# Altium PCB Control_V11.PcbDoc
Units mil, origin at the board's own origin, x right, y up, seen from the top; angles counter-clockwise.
Board outline 4960.63 x 3543.31 mil, 2 copper layers (TopLayer, BottomLayer); 68 components, 61 nets, 280 pads, 236 vias.
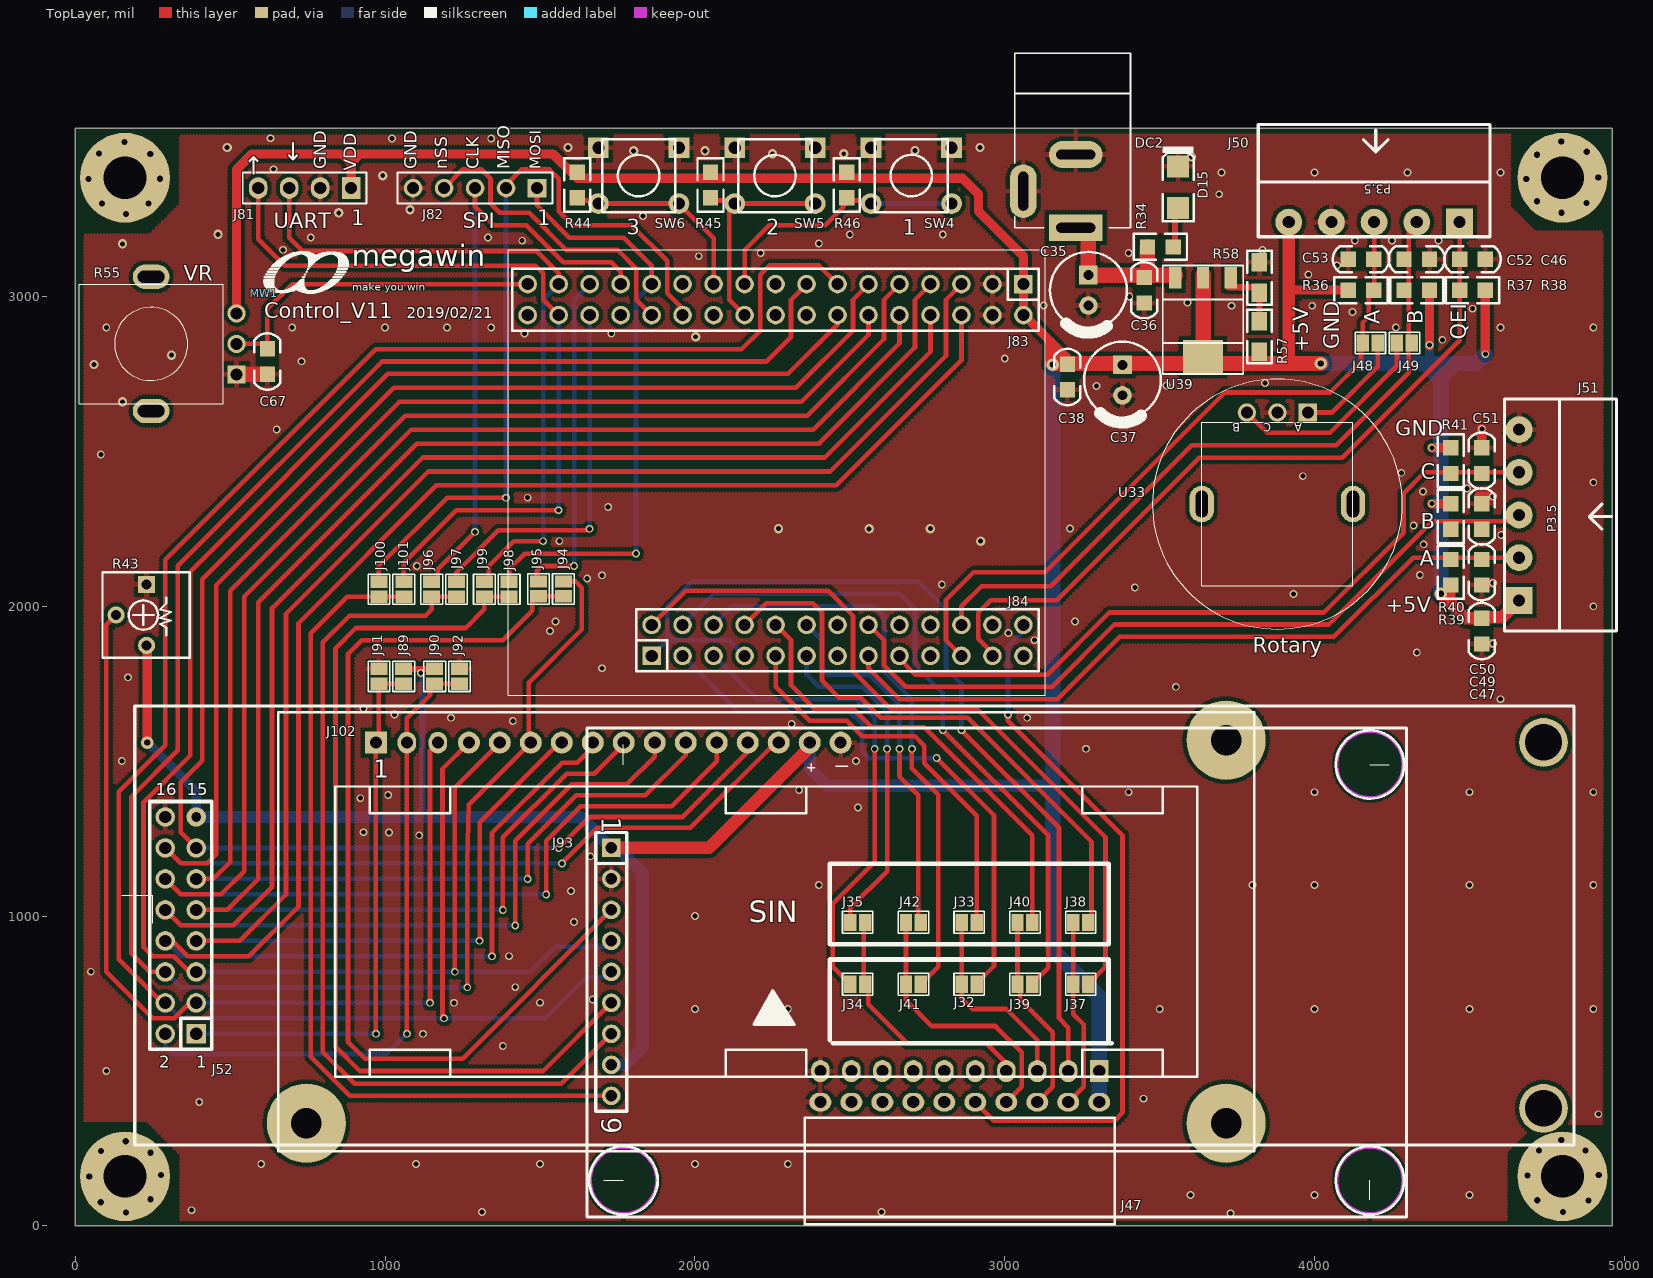
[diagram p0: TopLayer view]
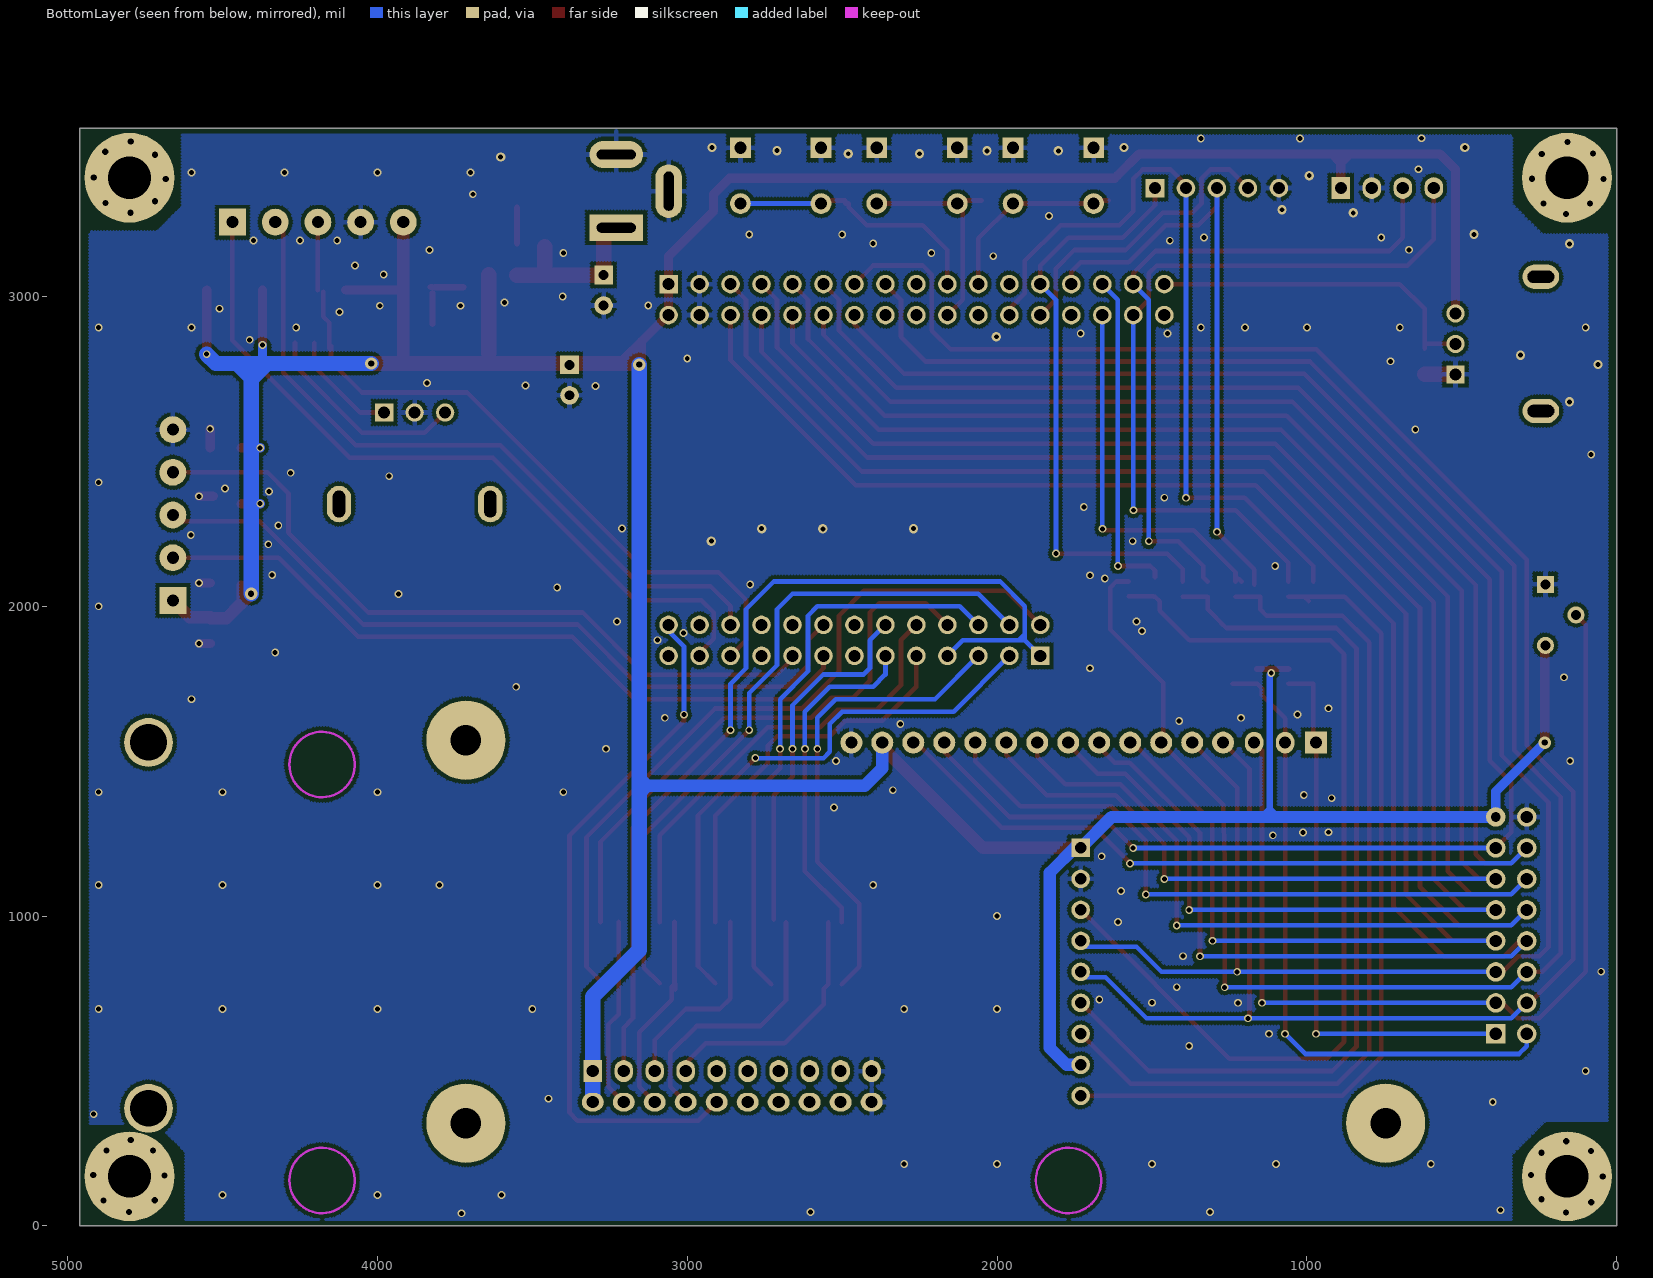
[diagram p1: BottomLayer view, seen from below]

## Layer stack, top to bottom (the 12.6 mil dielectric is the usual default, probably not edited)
TopLayer: signal copper 1.4
Dielectric: dielectric 12.6, FR-4, Dk 4.8
BottomLayer: signal copper 1.4

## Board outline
0,0 0,3543.31 4960.63,3543.31 4960.63,0

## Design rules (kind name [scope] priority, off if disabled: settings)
Clearance 20 [All] p1 off: gap=20
Clearance 12 [All] p2 off: gap=12
Clearance 6 [All] p3: gap=6
FabricationTestPointUsage TestPointUsage [All] p1: valid=0 allowmultiple=FALSE
FabricationTestpoint Testpoint [All] p1: side=3 testpointundercomponent=TRUE minsize=40 maxsize=100 preferedsize=60 minholesize=20 maxholesize=40 preferedholesize=32 testpointgrid=1 allowsidetop=TRUE allowsidebottom=TRUE usegrid=TRUE gridtolerance=0.01
HoleSize [All] p1: absolutevalues=TRUE maxlimit=500 minlimit=1 maxpercent=80.000 minpercent=20.000
PolygonConnect VIA [isvia] p1: connectstyle=Direct reliefconductorwidth=10 reliefentries=4 polygonreliefangle="90 Angle"
PolygonConnect PolygonConnect_1 [All] p2: connectstyle=Relief reliefconductorwidth=15 reliefentries=4 polygonreliefangle="90 Angle"
RoutingPriority [All] p1: routingpriority=4
RoutingVias [All] p1: holewidth=16 width=25 viastyle="Through Hole" minholewidth=16 minwidth=24 maxholewidth=28 maxwidth=50
SilkscreenOverComponentPads [All] p1: minsilkscreentomaskgap=10
SolderMaskExpansion [All] p1: expansion=4
Width [All] p1: maxlimit=100 minlimit=8 preferedwidth=10
23 further rules are at their usual default settings.

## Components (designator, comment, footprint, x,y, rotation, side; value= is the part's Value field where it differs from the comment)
C35 "47u" CEC063P025 3270,3020 r270 top
C36 "0.1u" 0805C 3450,3020 r270 top
C37 "47u" CEC063P025 3380,2730 r270 top
C38 "0.1u" 0805C 3202.32,2740 r270 top
C46 "0.1u" 0805C 4510,3120 r0 top
C47 "0.1u" 0805C 4540,1920 r270 top
C49 "0.1u" 0805C 4540,2110 r270 top
C50 "0.1u" 0805C 4540,2290 r90 top
C51 "0.1u" 0805C 4540,2470 r90 top
C52 "0.1u" 0805C 4150,3120 r180 top
C53 "0.1u" 0805C 4330,3120 r0 top
C67 "0.1u" 0805C 620,2790 r270 top
D15 "1206" 1206D 3560,3353.07 r90 top
DC2 "DC JACK" JACK_DC_0 3217.79,3336.28 r270 top
J32 "SP" JUMP2_SMD 2885.32,780 r180 top
J33 "SP" JUMP2_SMD 2885.32,980 r180 top
J34 "SP" JUMP2_SMD 2525.32,780 r0 top
J35 "SP" JUMP2_SMD 2525.32,980 r0 top
J37 "SP" JUMP2_SMD 3245.32,780 r180 top
J38 "SP" JUMP2_SMD 3245.32,980 r180 top
J39 "SP" JUMP2_SMD 3065.32,780 r180 top
J40 "SP" JUMP2_SMD 3065.32,980 r180 top
J41 "SP" JUMP2_SMD 2705.32,780 r180 top
J42 "SP" JUMP2_SMD 2705.32,980 r180 top
J47 "CON20A" PS10X2P254F_90 3305,499.69 r180 top
J48 "SP" JUMP2_SMD 4180,2850 r180 top
J49 "SP" JUMP2_SMD 4290,2850 r0 top
J50 "QEI Encoder" PW5P3.5_90 4467.8,3240 r180 top
J51 "HALL SENSOR" PW5P3.5_90 4660.32,2019.06 r90 top
J52 "LCM 16X2" PCB_16LCD118X36 390.32,620 r0 top locked
J81 "UART0" PS4P254 890.32,3350 r180 top
J82 "STD-SPI" PS5P254 1490.32,3350 r180 top
J83 "CON17x2" PS17X2P254 3060.32,3040 r180 top
J84 "CON26A" PS13X2P254 1860.32,1840 r0 top
J89 "SP" JUMP2_SMD 1060,1774 r270 top
J90 "SP" JUMP2_SMD 1160,1774 r270 top
J91 "SP" JUMP2_SMD 980,1774 r270 top
J92 "SP" JUMP2_SMD 1240,1774 r270 top
J93 "CON9" "PCB9_LCD_QVGA 2.2 TFT SPI" 1730,820 r270 top locked
J94 "SP" JUMP2_SMD 1575.32,2056 r270 top
J95 "SP" JUMP2_SMD 1495.32,2056 r270 top
J96 "SP" JUMP2_SMD 1150.32,2055 r270 top
J97 "SP" JUMP2_SMD 1230.32,2055 r270 top
J98 "SP" JUMP2_SMD 1400.32,2055 r270 top
J99 "SP" JUMP2_SMD 1320.32,2055 r270 top
J100 "SP" JUMP2_SMD 980,2055 r270 top
J101 "SP" JUMP2_SMD 1060.32,2055 r270 top
J102 "CON16" LCD16P80X31.4 655.35,241.1 r0 top locked
MW1 "MW-A4" MEGAWIN_3.4 610.32,3010 r0 top
R34 "1K" 0805R 3502.32,3160 r0 top
R36 "10K" 0805R 4150,3020 r0 top
R37 "10K" 0805R 4330,3020 r0 top
R38 "10K" 0805R 4510,3020 r0 top
R39 "10K" 0805R 4440,2110 r270 top
R40 "10K" 0805R 4440,2290 r90 top
R41 "10K" 0805R 4440,2470 r90 top
R43 "10K" vr3p 230,2070.68 r90 top
R44 "10K" 0805R 1620.32,3360 r270 top
R45 "10K" 0805R 2050.32,3360 r270 top
R46 "10K" 0805R 2490.32,3360 r270 top
R55 "10K" VR5P2.5 244.72,2846.89 r90 top
R57 "RESISTOR" 0805r 3822.32,2870.79 r90 top
R58 "RESISTOR" 0805r 3822.32,3060.79 r90 top
SW4 "START" SW_T 2698.32,3390 r270 top
SW5 "CW/CCW" SW_T 2258.32,3390 r270 top
SW6 "STOP" SW_T 1818.32,3390 r270 top
U33 "Rotary Encoder" REC_3P 3880,2330 r180 top
U39 "LM317/SOT-223" sot223 3730,3060 r180 top

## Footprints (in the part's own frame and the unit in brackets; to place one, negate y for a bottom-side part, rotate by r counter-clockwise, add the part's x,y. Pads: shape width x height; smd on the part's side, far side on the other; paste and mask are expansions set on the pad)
0805C [mm]
  rect 1.25x1.25 smd: 1(-1.05,0) 2(1.05,0)
  silkscreen extent -2.31,-1.07 2.31,1.07
0805R [mm]
  rect 1.25x1.25 smd: 1(-1.05,0) 2(1.05,0)
  silkscreen extent -2.18,-1.07 2.18,1.07
0805r [mil]
  rect 60x50 smd: 1(-49.21,0) 2(49.21,0)
  silkscreen extent -87,-40 87,40
1206D [mm]
  rect 1.8x1.8 smd: 1(-1.7,0) 2(1.7,0)
  silkscreen extent -2.8,-1.27 3.31,1.28
CEC063P025 [mil]
  rect 60x60 hole 31.5: 1(-49.21,0)
  round 60 hole 31.5: 2(49.21,0)
  silkscreen extent -124,-124 137,124
JACK_DC_0 [mm]
  rect 2.2x4.4 hole 0.8 slot 3.2 at 90 deg: 1(2.905,0.292)
  oval 4.4x2.2 hole 0.8 slot 3.2 at 0 deg: 2(-0.095,-4.008)
  oval 2.2x4.4 hole 0.8 slot 3.2 at 90 deg: 3(-3.095,0.292)
  silkscreen extent -11.39,-4.71 2.91,4.79
JUMP2_SMD [mil]
  rect 40x55 smd: 1(-24,0) 2(24,0)
  silkscreen extent -49,-35 49,35
LCD16P80X31.4 [mm]
  round 6.5 hole 2.5: 0(2.3,2.3) 0(77.7,2.3) 0(77.7,33.7)
  round 6.5 on Mech2: 0(2.3,33.7)
  rect 1.8x1.8 hole 1: 1(8,33.5)
  oval 1.524x1.778 hole 1: 2(10.54,33.5) 3(13.08,33.5)
  round 1.8 hole 1: 4(15.62,33.5) 5(18.16,33.5) 6(20.7,33.5) 7(23.24,33.5) 8(25.78,33.5) 9(28.32,33.5) 10(30.86,33.5) 11(33.4,33.5) 12(35.94,33.5) 13(38.48,33.5) 14(41.02,33.5) 15(43.56,33.5) 16(46.1,33.5)
  silkscreen extent 0,0 80,36
MEGAWIN_3.4 [mil]
  silkscreen extent -2,0 272,135
"PCB9_LCD_QVGA 2.2 TFT SPI" [mil]
  rect 60x60 hole 37: 1(-400,0)
  round 60 hole 37: 2(-300,0) 3(-200,0) 4(-100,0) 5(0,0) 6(100,0) 7(200,0) 8(300,0) 9(400,0)
  silkscreen extent -787,-79 791,2567
PCB_16LCD118X36 [mm]
  round 4 hole 3: 0(110.46,-6.11) 0(110.46,23.89)
  rect 1.6x1.6 hole 1: 1(0,0)
  round 1.6 hole 1: 2(-2.54,0) 3(0,2.54) 4(-2.54,2.54) 5(0,5.08) 6(-2.54,5.08) 7(0,7.62) 8(-2.54,7.62) 9(0,10.16) 10(-2.54,10.16) 11(0,12.7) 12(-2.54,12.7) 13(0,15.24) 14(-2.54,15.24) 16(-2.54,17.78)
  round 1.6 hole 0.8: 15(0,17.78)
  silkscreen extent -5.04,-9.11 112.96,26.89
PS4P254 [mil]
  rect 60x70 hole 39.37: 1(0,0)
  oval 60x70 hole 39.37: 2(100,0) 3(200,0) 4(300,0)
  silkscreen extent -50,-50 350,50
PS5P254 [mil]
  rect 60x60 hole 39.37: 1(0,0)
  round 60 hole 39.37: 2(100,0) 3(200,0) 4(300,0) 5(400,0)
  silkscreen extent -50,-50 450,50
PS10X2P254F_90 [mil]
  rect 60x71 hole 39.37: 1(0,0)
  oval 71x60 hole 39.37: 2(0,100) 4(100,100) 6(200,100) 8(300,100) 10(400,100) 12(500,100) 14(600,100) 16(700,100) 18(800,100) 20(900,100)
  oval 60x71 hole 39.37: 3(100,0) 5(200,0) 7(300,0) 9(400,0) 11(500,0) 13(600,0) 15(700,0) 17(800,0) 19(900,0)
  silkscreen extent -50,150 950,494
PS13X2P254 [mil]
  rect 60x60 hole 39.37: 1(0,0)
  round 60 hole 39.37: 2(0,100) 3(100,0) 4(100,100) 5(200,0) 6(200,100) 7(300,0) 8(300,100) 9(400,0) 10(400,100) 11(500,0) 12(500,100) 13(600,0) 14(600,100) 15(700,0) 16(700,100) 17(800,0) 18(800,100) 19(900,0) 20(900,100) 21(1000,0) 22(1000,100) 23(1100,0) 24(1100,100) 25(1200,0) 26(1200,100)
  silkscreen extent -50,-50 1250,150
PS17X2P254 [mil]
  rect 60x60 hole 39.37: 1(0,0)
  round 60 hole 39.37: 2(0,100) 3(100,0) 4(100,100) 5(200,0) 6(200,100) 7(300,0) 8(300,100) 9(400,0) 10(400,100) 11(500,0) 12(500,100) 13(600,0) 14(600,100) 15(700,0) 16(700,100) 17(800,0) 18(800,100) 19(900,0) 20(900,100) 21(1000,0) 22(1000,100) 23(1100,0) 24(1100,100) 25(1200,0) 26(1200,100) 27(1300,0) 28(1300,100) 29(1400,0) 30(1400,100) 31(1500,0) 32(1500,100) 33(1600,0) 34(1600,100)
  silkscreen extent -50,-50 1650,150
PW5P3.5_90 [mm]
  rect 2.2x2.2 hole 1: 1(0,0)
  round 2.2 hole 1: 2(3.5,0) 3(7,0) 4(10.5,0) 5(14,0)
  silkscreen extent -2.5,-8 16.5,1.2
REC_3P [mm]
  oval 2x3 hole 1 slot 2.2 at 90 deg: 0(-6.2,0) 0(6.2,0)
  rect 1.5x1.5 hole 1: 1(-2.5,-7.5)
  round 1.5 hole 1: 2(0,-7.5) 3(2.5,-7.5)
  silkscreen extent -10.25,-10.25 10.25,10.25
sot223 [mil]
  rect 40x70 smd: 1(0,0) 2(90,0) 3(180,0)
  rect 129.92x110.24 smd: 2(90,255.91)
  silkscreen extent -40,-40 220,310
SW_T [mm]
  rect 1.7x1.7 hole 1: 1(-2.286,3.302) 1(-2.286,-3.302)
  round 1.7 hole 1: 2(2.286,3.302) 2(2.286,-3.302)
  silkscreen extent -3,-3 3,3
vr3p [mm]
  rect 1.4x1.4 hole 0.8: 1(0,0)
  round 1.4 hole 0.8: 2(-2.5,2.5) 3(-5,0)
  silkscreen extent -6.01,-3.54 0.99,3.61
VR5P2.5 [mm]
  oval 2x3 hole 1 slot 2.2 at 90 deg: 0(-5.5,0) 0(5.5,0)
  rect 1.5x1.5 hole 1: 1(-2.5,-7)
  round 1.5 hole 1: 2(0,-7) 3(2.5,-7)
  silkscreen extent -4.9,-5.9 4.9,5.9

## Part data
C35 C37: library part CAP
C36 C38 C46 C47 C49 C50 C51 C52 C53 C67: library part "CAP NP"
D15: library part LED_sc
DC2: library part JACK_DC2
J50 J51 J82: library part CON5
J52: library part CON16A
J81: library part CON4
MW1: library part MW_A4_1S
R34 R36 R37 R38 R39 R40 R41 R44 R45 R46: library part RESISTOR
R43 R55: library part "RESISTOR VAR"
SW4 SW5 SW6: library part "SW PUSHBUTTON"
U39: library part LM317/TO

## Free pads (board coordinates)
  round 290 hole 138 unplated: 1(160,160) 1(160,3383.31) 1(4800.63,160) 1(4800.63,3383.31)

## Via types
v1: diameter 25, hole 16, TopLayer to BottomLayer, tented both sides, 178 vias
v2: diameter 30, hole 20, TopLayer to BottomLayer, tented both sides, 32 vias
v3: diameter 30, hole 16, TopLayer to BottomLayer, tented both sides, 22 vias
v4: diameter 40, hole 20, TopLayer to BottomLayer, tented both sides, 4 vias

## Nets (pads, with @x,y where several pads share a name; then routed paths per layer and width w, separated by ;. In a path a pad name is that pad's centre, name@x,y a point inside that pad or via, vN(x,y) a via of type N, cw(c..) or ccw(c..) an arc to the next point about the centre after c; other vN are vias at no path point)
ACM_UH: J47.3 J84.1 J84.7 | length 3123.9
  TopLayer w15: v1(2860.32,1600) 3175.32,1285 3175.32,669.69 3205,640 J47.3 ; J47.3@3215,479.69 J47.3@3215,499.69
  BottomLayer w15: J84.1 1910.32,1890 ; J84.7 2110.32,1890 1930.32,1890 ; v1(2860.32,1600) 2860.32,1750 2810.32,1800 2810.32,1990 2720.32,2080 1990.32,2080 1910.32,2000 1910.32,1910 ; 1910.32,1890 1930.32,1890 ; 1910.32,1890 1910.32,1910 ; 1910.32,1910 1930.32,1890
ACM_UL: J38.1 J84.8 | length 1856.9
  TopLayer w15: J84.8 2230.32,2010 2380.32,2010 2410.32,1980 2410.32,1759.69 2465,1705 2535.32,1705 2600.32,1640 2880.32,1640 3280,1240.32 J38.1@3280,980
ACM_VH: J33.1 J84.9 | length 1298.9
  TopLayer w15: J84.9 2260.32,1739.69 2370,1630 2490.32,1630 2540.32,1580 2710.32,1580 2740.32,1550 2740.32,1493.12 2909.32,1324.12 J33.1
ACM_VL: J40.1 J84.10 | length 1476.4
  TopLayer w15: J84.10 2310.32,1890 2310.32,1744.69 2390,1665 2515.32,1665 2570.32,1610 2740.32,1610 3089.32,1261 J40.1
ACM_WH: J35.1 J84.11 | length 1099
  TopLayer w15: J35.1 2501.32,1026.32 2620.32,1145.32 v1(2620.32,1540)
  BottomLayer w15: J84.11 2360.32,1780 2400.32,1740 2540.32,1740 2620.32,1660 v1(2620.32,1540)
ACM_WL: J42.1 J84.12 | length 1176.3
  TopLayer w15: v1(2660.32,1540) 2660.32,1449.69 2720.32,1389.69 J42.1@2720.32,989
  BottomLayer w15: J84.12 2410.32,1890 2410.32,1800 2430.32,1780 2560.32,1780 2660.32,1680 v1(2660.32,1540)
ADC_VR_IN: C67.1 J83.33 R55.2 | length 1101.8
  TopLayer w15: R55.2 C67.1@620,2846.89 ; C67.1 C67.1@620,2846.89 ; J83.33 700,3040 620,2960 C67.1@620,2846.89
BLDC_UL: J37.1 J84.2 | length 2443.5
  TopLayer w15: J84.2 1970.32,2050 2430.32,2050 2510.32,1970 2510.32,1790 2630.32,1670 2910.32,1670 3325.32,1255 3325.32,836 J37.1
BLDC_VH: J32.1 J84.3 | length 1836.6
  TopLayer w15: v1@2780.32,1509.69 v1(2780.32,1510) 2965.32,1325 2965.32,839 J32.1@2909.32,783
  BottomLayer w15: J84.3 2140.32,1660 2500.32,1660 2540.32,1620 2540.32,1530 2560.32,1510 v1(2780.32,1510)
BLDC_VL: J39.1 J84.4 | length 2218.1
  TopLayer w15: v1(2800.32,1600) 3140,1260.32 3140,833.69 J39.1@3089.32,783
  BottomLayer w15: J84.4 2060.32,2040 2660.32,2040 2710.32,1990 2710.32,1810 2800.32,1720 v1(2800.32,1600)
BLDC_WH: J34.1 J84.5 | length 1542
  TopLayer w15: J34.1 2445.32,836 2445.32,1040.32 2580.32,1175.32 v1(2580.32,1540)
  BottomLayer w15: J84.5 2200.32,1700 2520.32,1700 2580.32,1640 v1(2580.32,1540)
BLDC_WL: J41.1 J84.6 | length 1873
  TopLayer w15: v1(2700.32,1540) 2700.32,1476.55 2785.32,1391.55 2785.32,836 J41.1
  BottomLayer w15: J84.6 2120.32,2000 2580.32,2000 2610.32,1970 2610.32,1790 2700.32,1700 v1(2700.32,1540)
FAULT: J47.10 J84.26 | length 2259.2
  TopLayer w15: J47.10 2965,339.69 3354.68,339.69 3380,365 3380,1260.32 3010.32,1630 v1(3010.32,1650)
  BottomLayer w15: v1(3010.32,1650) 3010.32,1870 J84.26@3060.32,1920 ; 3050,1910 J84.26@3050,1930
GND_S: C35.2 C36.2 C37.2 C38.2 C46.2 C47.2 C49.2 C50.2 C51.2 C52.2 C53.2 C67.2 D15.2 DC2.2 DC2.3 J47.19 J47.20 J50.4 J51.5 J52.16 J81.2 J82.5 J83.3 J83.4 J91.1 J92.1 J93.2 J102.16 R43.1 R55.1 R58.2 SW4.1 SW5.1 SW6.1 U33.2 | length 304.2
  TopLayer w30: J102.16@2460.32,1570 J102.16@2470.32,1580 ; C50.2@4530,2355 4540,2355 v1(4576.34,2355) ; C47.2@4540,1880 v1(4576.34,1880) ; C49.2@4540,2075 v1(4576.34,2075) ; C51.2 v1(4540,2572.68)
  TopLayer w50: R55.1@520.32,2748.66 C67.2
  BottomLayer w20: J52.16 J52.16@300.32,1320
  other v1: 3729,40.68 1312.32,45 2602.32,45 375,50.68 3600,100 4000,100 4500,100 600,200 1100,200 1500,200 2000,200 2300,200 4916,360.68 400,400 3448,410.68 100,500 1380,580.68 1122.32,620 2000,700 2300,700 3500,700 4000,700 4500,700 4900,700 1222.32,720 1500,720.68 1670,730.68 1420,770.68 50,820.68 1400,870.68 1610,980.68 2000,1000 1600,1080.68 2400,1100 3800,1100 4000,1100 4500,1100 4900,1100 1662.32,1193 1110,1260.68 1012.32,1270 930,1270.68 2526,1350.68 920,1380.68 1010,1390.68 3400,1400 4000,1400 4500,1400 4900,1400 2336.57,1406.26 150,1500.68 2520,1500.68 3262.32,1540 2312.32,1620 1412.32,1630 1212.32,1640 3072.32,1640 1030,1650.68 930,1670.68 4600,1700 3552.32,1740 170,1770.68 1700,1800 4330,1850.68 3096,1890.68 3012,1914 1532.32,1920 1550,1950.68 3227,1950.68 4900,2000 3932.32,2040 3420,2060.68 2797,2070.68 1652.32,2090 1700,2100 4340,2100.68 1102.32,2130 4352.32,2200 1562.32,2210 4602.32,2230 3211,2250.68 4320,2260.68 1720,2320.68 1460,2350.68 4350,2370.68 4492.32,2380 4900,2400 3962.32,2420 4280,2430.68 82.32,2490 650,2570.68 3296,2710.68 3522.32,2713 3840,2720.68 730,2790.68 3000,2800 4412.32,2860 1450,2880.68 1730,2880.68 100,2900 700,2900 1000,2900 1200,2900 1342.32,2900 4262.32,2900 4600,2900 4900,2900 4122.32,2950 4510,2960.68 3732.32,2970 3992.32,2970 3126,2970.68 3590,2980.68 3402.32,3000 3980,3070.68 4072.32,3100 2012.32,3130 2212.32,3140 3400,3140.68 3832.32,3150 670,3150.68 2400,3170.68 1442.32,3180 4130,3180.68 4250,3180.68 4400,3180.68 1332.32,3190 760,3190.68 2500,3200 2800,3200 1832.32,3260 3692.32,3330 3700,3400 4000,3400 4300,3400 4600,3400 640,3410.68 1022.32,3510 1342.32,3510 630,3510.68
  other v3: 2922.32,2210 2562.32,2250 2270,2250.68 2760,2250.68 152.32,2660 60.32,2780.68 310.32,2810.68 2002.32,2870 152.32,3170 460.32,3200.68 850.32,3270 1080.32,3280 992.32,3390 3602.32,3450 2250.32,3460.68 2480.32,3460.68 1802.32,3470 2032.32,3470 2710.32,3470.68 490.32,3480.68 1590.32,3480.68 2920,3480.68
HALL_H1: C49.1 J51.2 J84.15 R39.1 | length 2370.7
  TopLayer w15: J84.15 2560.32,1800 2660.32,1700 3169.52,1700 3370.69,1901.17 4062.65,1901.17 4318.34,2156.85 J51.2
HALL_H2: C50.1 J51.3 J84.16 R40.1 | length 2459.4
  TopLayer w15: J84.16 2610.32,1890 2610.32,1810 2680.32,1740 3152.95,1740 3354.12,1941.17 4046.09,1941.17 4379.92,2275 4640.67,2275 J51.3
HALL_H3: C51.1 J51.4 J84.17 R41.1 | length 2376
  TopLayer w15: J84.17 2660.32,1830 2711.48,1778.83 3136.87,1778.83 3338.03,1980 4030,1980 4287.32,2237.32 4287.32,2364.32 4354.76,2431.77 ; 4354.76,2432.44 4540,2432.44 J51.4
LCM_D0: J52.7 J83.5 J102.7 | length 5664
  TopLayer w15: J52.7 530.32,920 680,1069.69 680,1975.6 1139.55,2435.15 2437.3,2435.15 2810.32,2808.16 2810.32,2990 J83.5 ; v1(1305,920) 1305,1302.89 J102.7@1566.22,1564.1 ; J102.7@1566.22,1539.1 1570.32,1543.2 J102.7@1570.32,1555
  BottomLayer w15: J52.7 v1@1299.1,920
LCM_D1: J52.8 J83.6 J102.8 | length 5993
  TopLayer w15: J52.8 313.32,920 363.32,870 560.32,870 720.32,1030 720.32,1945 1165.47,2390.15 2455.94,2390.15 2860.32,2794.52 J83.6 ; v1(1345,870) 1345,1268.39 1571.61,1495 1620.32,1495 1670.32,1545 J102.8@1670.32,1555
  BottomLayer w15: J52.8 340.32,870 v1(1345,870)
LCM_D2: J52.9 J83.7 J102.9 | length 5559.1
  TopLayer w15: J52.9 490.32,1020 590,1119.69 590,2012.88 1102.27,2525.15 2400.02,2525.15 2710.32,2835.44 2710.32,2990 J83.7 ; v1(1380,1020) 1380,1253.89 1586.11,1460 1675.32,1460 J102.9@1770.32,1555
  BottomLayer w15: J52.9 v1(1380,1020)
LCM_D3: J52.10 J83.8 J102.10 | length 5929.1
  TopLayer w15: J52.10 340.32,970 510.32,970 635,1094.69 635,1994.24 1120.91,2480.15 2418.66,2480.15 2760.32,2821.8 J83.8 ; v1(1420,970) 1420,1242.67 1602.33,1425 1780.32,1425 1870.32,1515 J102.10@1870.32,1555
  BottomLayer w15: J52.10 340.32,970 v1(1420,970)
LCM_D4: J52.11 J83.9 J102.11 | length 5499.7
  TopLayer w15: J52.11 445.35,1120 500,1174.65 500,2050.16 1064.99,2615.15 2362.74,2615.15 2610.32,2862.72 2610.32,2990 J83.9 ; v1(1460,1120) 1460,1233.18 1616.82,1390 1840.32,1390 1970.32,1520 J102.11@1970.32,1555
  BottomLayer w15: J52.11 v1(1460,1120)
LCM_D5: J52.12 J83.10 J102.12 | length 5898.6
  TopLayer w15: J52.12 340.32,1070 470.32,1070 545,1144.69 545,2031.52 1083.63,2570.15 2381.38,2570.15 2660.32,2849.08 J83.10 ; v1(1520,1070) 1520,1243.68 1631.32,1355 1925.32,1355 2070.32,1500 J102.12 J102.12@2070.32,1580
  BottomLayer w15: J52.12 340.32,1070 v1(1520,1070)
LCM_D6: J52.13 J83.11 J102.13 | length 5479.1
  TopLayer w15: J52.13 340.32,1270 340.32,1432.32 410,1502 410,2087.44 1027.71,2705.15 2325.47,2705.15 2510.32,2890 2510.32,2990 J83.11 ; v1@1560.34,1220.34 1660,1320 1960.32,1320 2170.32,1530 J102.13 J102.13@2170.32,1580
  BottomLayer w15: J52.13 v1(1560.68,1220)
LCM_D7: J52.14 J83.12 J102.14 | length 5747
  TopLayer w15: J52.14 340.32,1170 425.35,1170 455,1199.65 455,2068.8 1046.35,2660.15 2344.11,2660.15 2560.32,2876.36 J83.12 ; v1@1570.5,1170.5 1685,1285 1985.32,1285 2270.32,1570 J102.14@2270.32,1580
  BottomLayer w15: J52.14 340.32,1170 v1(1570.99,1170)
LCM_EN: J52.6 J83.15 J94.1 J102.6 | length 6465.4
  TopLayer w15: J52.6 240.32,820 180.32,880 180.32,1384.48 330.69,1534.85 330.69,2130.69 990,2790 2230.32,2790 2310.32,2870 2310.32,2990 J83.15 ; v1(1265.32,770) 1265.32,1175 1270.32,1360 J102.6 J102.6@1470.32,1580 ; J102.6@1463.75,1566.56 1463.75,1753.75 1635,1925 1635,1990 ; J94.1 1615,2080 1635,2060 1635,1990 ; 1635,1970 1635,1990
  BottomLayer w15: J52.6 340.32,770 v1(1265.32,770)
LCM_LED_ANODE: C37.1 C38.1 C47.1 J47.1 J47.2 J50.5 J51.1 J52.15 J81.1 J83.1 J83.2 J89.1 J90.1 J93.1 J93.8 J102.15 R36.1 R37.2 R38.2 R39.2 R40.2 R41.2 R43.3 R44.1 R45.1 R46.1 R55.3 R57.1 U39.2 | length 15913.9
  TopLayer w15: 862.56,3448.07 890.32,3420.32 930,3460
  TopLayer w20: J89.1 1115,1798 J90.1
  TopLayer w30: v4(232.32,1560) 232.32,1873.83 R43.3@232.32,1880 ; R55.3 520.32,3410 570.32,3460 890.32,3460 ; J81.1 890.32,3420.32 890.32,3460 ; J102.15 2360.32,1570 J102.15@2370.32,1580 ; J102.15@2377.82,1552.5 J102.15@2385.32,1560 ; J83.2 J83.1 3060.32,3130 2915,3275.32 2915,3330 2863.66,3381.34 2490.32,3381.34 2050.32,3381.34 1620.32,3381.34 1610.32,3391.34 1541.65,3460 930,3460 890.32,3460 ; J83.2@3061.32,2941 3148.42,2853.89 ; v4@3148.42,2780 3148.42,2853.89 ; v4@3155,2790.67 v4@3170,2790.67 ; 3170,2816.78 v4@3170,2790.67 ; C38.1@3202.32,2800 3148.42,2853.89 ; C38.1@3220,2780 3216.34,2783.66 3210.49,2789.51 3209.33,2790.67 3202.32,2790.67 v4@3170,2790.67 ; 3923.78,3020.68 R36.1@4102.32,3020.68 ; v1@4371.34,2840 v1(4371.34,2843.66) R37.2 ; v1(4378.66,2331.34) R40.2 ; v1(4378.66,2511.34) R41.2 ; 4440,2008.68 4440,2040.68 R39.2 ; v1@4551.34,2820 R38.2
  TopLayer w40: J93.1 2045.32,1220 J102.15@2377.82,1552.5 ; 3916.61,2783.66 J50.5 ; v4@4409.65,2039.02 4410.01,2038.67 4440,2008.68 4487.34,1961.34 C47.1 ; C47.1@4540,1965 4606.26,1965 J51.1
  TopLayer w50: v4@3155,2783.66 3202.32,2783.66 3216.34,2783.66 3380,2783.66 3640,2783.66 3822.32,2783.66 3916.61,2783.66 v4(4020,2783.66) ; U39.2@3640,2814.77 3640,3060 U39.2@3640,3070.68
  BottomLayer w15: 1090,1320 1120,1350 1150,1320 ; 3110.52,1420.52 3155,1376.04 ; 3111.04,1421.04 3145,1455 ; 3145,1690 3155,1680
  BottomLayer w20: v1(1115,1785) 1120,1780 1120,1350 1120,1320
  BottomLayer w30: v4(232.32,1560) 390.32,1402 J52.15 ; 472.32,1320 477.47,1314.84 ; 1275,1320 1295,1320 ; 4371.34,2783.66 v1@4371.34,2840.68 ; v1(4378.66,2331.34) 4408,2331.34 4408.66,2331.34 ; v1(4378.66,2511.34) 4408,2511.34
  BottomLayer w40: J52.15 472.32,1320 1090,1320 1120,1320 1150,1320 1275,1320 1630,1320 J93.1 ; J93.8 1775.25,520 1830,574.75 1830,1140 J93.1@1745,1225 ; J102.15 2370.32,1477.67 2426.95,1421.04 3111.04,1421.04 3155,1421.04 ; 4352.32,2781.66 4408,2725.98 ; 4408,2783.66 4408,2731.66 ; 4408.15,2725.83 4408,2725.98 ; 4460,2783.66 4408,2731.66 ; 4408,2725.98 4408,2731.66
  BottomLayer w50: v4(3155,2780) 3155,1680 3155,1421.04 3155,1376.04 3155,890 3305,740 J47.1 J47.2 ; v4(4020,2783.66) 4371.34,2783.66 4408,2783.66 4460,2783.66 4521.34,2783.66 v1(4551.34,2813.66) ; v4(4408,2040.68) 4408,2331.34 4408,2511.34 4408,2725.98
LCM_PIN1: J52.1 J89.2 J91.2 J102.1 | length 1846.8
  TopLayer w15: J52.1@390,620 390,615 410,615 405,620 J52.1 ; v1(970.32,620) J102.1 J102.1@970.32,1580 ; J102.1@980,1570 J91.2 J89.2
  BottomLayer w15: J52.1 v1(970.32,620)
LCM_PIN2: J52.2 J90.2 J92.2 J102.2 | length 2169.9
  TopLayer w15: J52.2@290,620 290,619.69 J52.2 ; J52.2@290.32,600 J52.2 ; J52.2@315,620 J52.2 ; v1(1070.32,620) J102.2 ; J102.2@1070.32,1580 J102.2 ; J92.2 J90.2 1145,1735 1145,1713.66 1070.32,1638.98 J102.2
  BottomLayer w15: J52.2 290.32,580 315.32,555 1005.32,555 v1(1070.32,620)
LCM_RS: J52.4 J83.13 J93.5 J102.4 | length 6699
  TopLayer w15: J52.4 280.32,720 140.32,860 140.32,1401.05 290.69,1551.42 290.69,2150.69 970,2830 2150.32,2830 2210.32,2890 2210.32,3070 2240.32,3100 2400.32,3100 J83.13 ; v1(1190,670) 1185,675 1185,1474.69 J102.4 J102.4@1270.32,1580
  BottomLayer w15: J52.4 340.32,670 v1(1190,670) 1517.7,670 1650,802.3 J93.5@1712.3,802.3
LCM_RW: J52.5 J83.14 J93.4 J102.5 | length 6122.8
  TopLayer w15: J52.5@367.32,820 317.32,870 250.32,870 220.32,900 220.32,1367.91 370.69,1518.28 370.69,2111.77 1009.07,2750.15 2300.47,2750.15 2460.32,2910 J83.14 ; v1(1225,820) 1225,1414.69 J102.5 J102.5@1370.32,1580
  BottomLayer w15: J52.5 1190.32,820 ; 1210.32,820 1190.32,820 ; J93.4@1735,900.68 1550,900.68 1469.32,820 v1(1225,820) 1190.32,820
LCM_VO: J52.3 J102.3 R43.2 | length 3163.2
  TopLayer w15: R43.2 100.32,1940.99 100.32,820 250.32,670 320,670 370,720 J52.3 ; v1(1145,720) 1145,1534.69 J102.3 J102.3@1170.32,1580
  BottomLayer w15: J52.3 v1(1145,720)
NetC35_1: C35.1 C36.1 DC2.1 R34.1 U39.3 | length 482.8
  TopLayer w50: DC2.1@3270,3181.18 C35.1 U39.3@3550,3069.21 ; C36.1@3460,3069.89 R34.1@3460,3160.68
NetD15_1: D15.1 R34.2 | length 114.8
  TopLayer w20: R34.2@3550,3171.34 D15.1@3550,3286.14
NetJ32_2: J32.2 J33.2 J47.5 | length 675.7
  TopLayer w15: 2861.32,736 2861.32,745 ; J33.2@2861.32,981 J33.2 J32.2 2861.32,745 ; J47.5 3105,600 3005,700 2895,700 2861.32,733.69 2861.32,745 ; J47.5@3115,479.69 J47.5@3115,499.69
NetJ34_2: J34.2 J35.2 J47.7 | length 840.1
  TopLayer w15: J35.2@2545.32,980 2545.32,780 2560,765.32 2560,715 2685,590 2940,590 3005,525 J47.7 ; J47.7@3015,479.69 J47.7@3015,499.69
NetJ37_2: J37.2 J38.2 J47.4 | length 625
  TopLayer w15: J47.4 3255,449.69 3255,650 3221.32,683.69 3221.32,745 ; 3221.32,736 3221.32,745 ; J38.2@3221.32,981 J38.2 J37.2 3221.32,745
NetJ39_2: J39.2 J40.2 J47.6 | length 673.4
  TopLayer w15: J39.2@3038.32,763 3038.32,783 J39.2@3041.32,786 ; J40.2@3041.32,981 J40.2 J39.2@3041.32,786 ; J47.6 3155,449.69 3155,625 3050,730 3050,771.32 J39.2 J39.2@3041.32,786
NetJ41_2: J41.2 J42.2 J47.8 | length 875.9
  TopLayer w15: J42.2 J41.2 2681.32,728.69 2765,645 2970,645 3055,560 3055,449.69 J47.8
NetJ48_1: J48.1 U33.1 | length 363.2
  TopLayer w15: U33.1 4055.28,2625.28 4204,2774 J48.1
NetJ49_1: J49.1 U33.3 | length 674.9
  TopLayer w15: U33.3 3846.85,2560 4050,2560 4266,2776 J49.1
NetR57_2: R57.2 R58.1 U39.1 | length 197.4
  TopLayer w20: U39.1@3722.32,3030 3729.9,3029.98 R58.1@3814.69,3029.7 ; R57.2@3822.32,2911.89 R57.2 R58.1 ; R58.1@3822.38,3030.38 R58.1@3827.68,3030.36
NMOTOR_PWM_EN: J47.18
PB_SW1: J83.19 R46.2 SW4.2 | length 887.2
  TopLayer w15: 2160.32,3110 J83.19 2160.32,3150 2240.32,3230 2420.32,3230 2478.32,3288 2478.32,3300 R46.2@2490.32,3300 ; R46.2@2490.32,3310 SW4.2@2538.32,3310
  BottomLayer w15: SW4.2@2568.32,3300 SW4.2@2828.32,3300
PB_SW2: J83.20 R45.2 SW5.2 | length 846.2
  TopLayer w15: R45.2@2050.32,3310 SW5.2@2098.32,3310 ; 2110.32,3140 2110.32,2990 ; J83.20 2110.32,2990 ; SW5.2@2388.32,3300 2128.32,3300 2110.32,3282 2110.32,2990
PB_SW3: J83.21 R44.2 SW6.2 | length 614.4
  TopLayer w15: R44.2@1640.32,3310 SW6.2@1688.32,3310 ; SW6.2@1688.32,3300 1948.32,3300 2060.32,3188 J83.21
QEI_A: C52.1 J48.2 J50.3 J84.21 R36.2 | length 2321.8
  TopLayer w15: J84.21 2810.32,1890 2810.32,2021.03 2899.29,2110 3130,2110 3710,2690 4050,2690 4150,2790 J48.2@4150,2840 ; J48.2@4156,2831 J48.2 4156,2916 4175,2935 R36.2@4175,3015 ; R36.2@4192.2,3020 J50.3
QEI_B: C53.1 J49.2 J50.2 J84.22 R37.1 | length 2313
  TopLayer w15: J84.22 2860.32,2000.32 2925,2065 3148.64,2065 3603.64,2520 4070,2520 4304,2754 4304,3214 J50.2
QEI_IDX: C46.1 J50.1 J84.23 R38.1 | length 2470.7
  TopLayer w15: J84.23 J84.23@2969.68,1840 ; J84.23@2970.32,1840 J84.23@2969.68,1840 ; J50.1@4468.66,3239.13 C46.1 R38.1 4468.66,2858.66 4090,2480 3627.28,2480 3167.28,2020 2955,2020 2915,1980 2915,1894.69 J84.23@2969.68,1840
SPI_LCM_CS: J93.3 J94.2 J95.2 | length 3111.9
  TopLayer w15: J95.2@1495.32,2031 1490.32,2031 1475.32,2016 1475.32,1985.32 1380,1890 925,1890 880,1845 880,595 935,540 1250,540 J93.3 ; J95.2 J94.2
SPI_LCM_SCK: J93.7 J96.2 J97.2 | length 2879.7
  TopLayer w15: J97.2 J96.2 1150.32,1990 1130.32,1970 885,1970 798.68,1883.68 798.68,561.32 901.32,458.68 1568.68,458.68 J93.7
SPI_LCM_SDI_MOSI: J93.6 J98.2 J99.2 | length 2975.3
  TopLayer w15: 1275.73,1945.73 1260,1930 ; J98.2 J99.2 1320.32,1990.32 1260,1930 ; J93.6 1510,500 918.43,500 840,578.43 840,1865 905,1930 1260,1930
SPI_LCM_SDO_MISO: J93.9 J100.2 J101.2 | length 2758.6
  TopLayer w15: J100.2@994,2017 1008,2031 ; J101.2 1008,2031 ; J93.9 885.29,420 760,545.29 760,1913 878,2031 J100.2 1008,2031
STD_SPI_CLK: J82.3 J83.27 J96.1 | length 1987.5
  TopLayer w15: J96.1@1170,2069.36 1170,2079 1170,2120 v1(1290.32,2240.32) ; J82.3 1290.32,3290 1350.32,3230 1455,3230 1575,3110 1730.32,3110 1760.32,3080 J83.27
  BottomLayer w15: v1(1290.32,2240.32) J82.3
STD_SPI_MISO: J82.2 J83.24 J100.1 | length 3401.8
  TopLayer w15: J100.1 980,2130 1200,2350 v1(1390,2350) ; J82.2 1390.32,3360 1440.01,3409.69 1530.62,3409.69 1560.32,3380 1560.32,3274.69 1605,3230 1795,3230 1910.32,3114.69 1910.32,3010 ; 1910.32,3110 1910.32,3010 ; J83.24 1960.32,2960 1910.32,3010
  BottomLayer w15: v1(1390,2350) 1390.32,2350.32 J82.2 1390.32,2530.32
STD_SPI_MOSI: J82.1 J83.25 J98.1 | length 1928.5
  TopLayer w15: J98.1 1400.32,2120.32 1450,2170 v1(1810,2170) ; J82.1 1490.32,3294.69 1595,3190 1770,3190 1860.32,3099.69 ; J83.25 1860.32,3099.69 ; 1860.32,3100 1860.32,3099.69
  BottomLayer w15: v1(1810,2170) 1810,2989.69 J83.25
STD_SPI_NSS: J82.4 J83.26 | length 995
  TopLayer w15: J82.4 1250.32,3410 1310.32,3410 1340.32,3380 1340.32,3300 1370.32,3270 1465,3270 1585,3150 1750.32,3150 1810.32,3090 1810.32,2990 J83.26
URT0_CLK: J83.30 J97.1 | length 1222.7
  TopLayer w15: J97.1@1210.32,2079 J97.1@1220.32,2089 ; J97.1 1230.32,2110.32 1365,2245 1655,2245 v1(1660,2250)
  BottomLayer w15: v1(1660,2250) J83.30@1660,2939.69
URT0_NSS: J83.29 J95.1 | length 1077.4
  TopLayer w15: J95.1@1490,2094.69 1490,2115 1505,2130 v1(1610,2130)
  BottomLayer w15: v1(1610,2130) 1610,2989.69 J83.29
URT0_RX: J81.4 J83.32 J101.1 | length 2547.2
  TopLayer w15: J81.4 590.32,3184.69 675.45,3099.55 1485.45,3099.55 1510.32,3074.69 1510.32,2990 J83.32 ; J101.1 1060.32,2140.32 1230,2310 v1(1560,2310)
  BottomLayer w15: v1(1560,2310) J83.32@1560,2939.69
URT0_TX: J81.3 J83.31 J99.1 | length 2228.7
  TopLayer w15: J81.3 690.32,3189.69 733.08,3146.92 1488.08,3146.92 1560.32,3074.69 J83.31 ; J99.1 1335,2093.69 1335,2130 1415,2210 v1(1510,2210)
  BottomLayer w15: v1(1510,2210) 1510,2989.69 J83.31
pads on no net: J47.9 J47.11 J47.12 J47.13 J47.14 J47.15 J47.16 J47.17 J52.0 J83.16 J83.17 J83.18 J83.22 J83.23 J83.28 J83.34 J84.13 J84.14 J84.18 J84.19 J84.20 J84.24 J84.25 J102.0 R55.0 U33.0
copper on no net:
  other v2: 164,43 4801.63,45 82,76 4884.63,82 4718.63,83 243,86 45,159 4687.63,163 277,164 4917.63,164 243,236 83,242 4724.63,243 4874.63,243 163,273 4796.63,277 164,3266.31 4797.63,3270.31 86,3300.31 236,3300.31 4877.63,3301.31 4717.63,3307.31 43,3379.31 4683.63,3379.31 273,3380.31 4915.63,3384.31 4717.63,3457.31 242,3460.31 76,3461.31 4878.63,3467.31 159,3498.31 4796.63,3500.31

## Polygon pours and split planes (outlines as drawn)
no net on TopOverlay "Top Layer-No Net" (hatched 90Degree grid 10 track 10, remove dead copper): 2251,760 2191,650 2321,650
GND_S on BottomLayer "Top Layer-No Net" (hatched 90Degree grid 10 track 10, remove dead copper, pour order 1000): 30,340 230,340 340,230 340,20 4620,20 4620,240 4710,330 4927.86,330 4930,3210 4710,3210 4630,3290 4630,3521.65 338,3519.65 338,3298 240,3200 30,3200
GND_S on TopLayer "Top Layer-No Net" (hatched 90Degree grid 10 track 10, remove dead copper, pour order 1000): 30,340 230,340 340,230 340,20 4620,20 4620,240 4710,330 4927.86,330 4930,3210 4710,3210 4630,3290 4630,3521.65 338,3519.65 338,3298 240,3200 30,3200

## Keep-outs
KeepOutLayer:
  circle w7.88: c4178.82,1489.29 r105.6
  circle w7.88: c4178.82,146.77 r105.6
  circle w7.88: c1769.37,146.77 r105.6

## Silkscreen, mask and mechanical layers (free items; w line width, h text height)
TopOverlay:
  lines w4: 150,1067.56 250,1067.56 250,977.56 ; 1398.03,1713.23 1398.03,3150.24 3130.32,3150.24 3130.32,1713.23 1398.03,1713.23
  lines w15: 2434.68,600 2434.68,860 3335,860 3335,600 ; 2444.68,589.69 3345,589.69 ; 2435,909 3335.32,909 3335.32,1169 2435,1169 2435,909
  text "↓" at 610.32,3470 h100 r180
  text "↓" at 670.32,3420 h100
  text "GND" at 1101.59,3411.27 h40 r90
  text "nSS" at 1200.72,3411.27 h40 r90
  text "CLK" at 1301.59,3411.27 h40 r90
  text "MISO" at 1401.59,3411.27 h40 r90
  text "MOSI" at 1501.59,3411.27 h35 r90
  text "GND" at 810.32,3410 h40 r90
  text "VDD" at 906.38,3406.06 h40 r90
  text "1" at 890.32,3230 h50
  text "1" at 1490.32,3230 h50
  text "UART" at 640.32,3220 h50
  text "SPI" at 1250.32,3220 h50
  text "3" at 1780,3200 h50
  text "2" at 2230,3200 h50
  text "1" at 2670.32,3200 h50
  text "VR" at 350,3050 h50
  text "Control_V11" at 610.32,2930 h50
  text "2019/02/21" at 1070.32,2930 h35
  text "A" at 4210,2910 h50 r90
  text "B" at 4350,2910 h50 r90
  text "QEI" at 4490,2860 h50 r90
  text "GND" at 4080,2830 h50 r90
  text "+5V" at 3980,2820 h50 r90
  text "GND" at 4260,2550 h50
  text "C" at 4342.32,2410 h50
  text "B" at 4342.32,2250 h50
  text "A" at 4340,2130.68 h50
  text "+5V" at 4230,1980 h50
  text "Rotary" at 3800,1850 h50
  text "SIN" at 2173,980 h70
Mechanical1:
  the board outline again, w8

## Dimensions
0,0 to 4960.63,0 on TopOverlay
0,0 to 0,3543.31 on TopOverlay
